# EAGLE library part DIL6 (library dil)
SOCKET Dual In Line
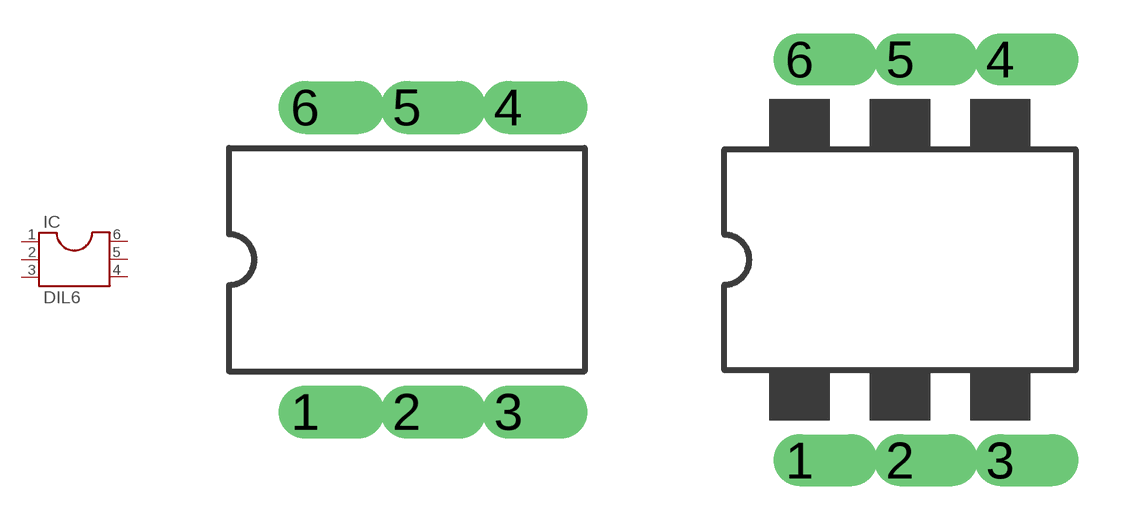
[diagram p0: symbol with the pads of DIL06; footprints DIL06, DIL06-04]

Designator prefix IC

## DIL6  [DIL06]
1  1  pas
2  2  pas
3  3  pas
4  4  pas
5  5  pas
6  6  pas

## DIL6/4  [DIL06-04]
Pads as for DIL06

## Footprint DIL06 (pad centres in mm)
SOCKET Dual In Line
drill 0.813 offset: 1 -2.54,-3.81; 2 0,-3.81; 3 2.54,-3.81; 4 2.54,3.81; 5 0,3.81; 6 -2.54,3.81

## Footprint DIL06-04 (pad centres in mm)
SOCKET Dual In Line, 0.4 inch
drill 0.813 offset: 1 -2.54,-5.08; 2 0,-5.08; 3 2.54,-5.08; 4 2.54,5.08; 5 0,5.08; 6 -2.54,5.08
